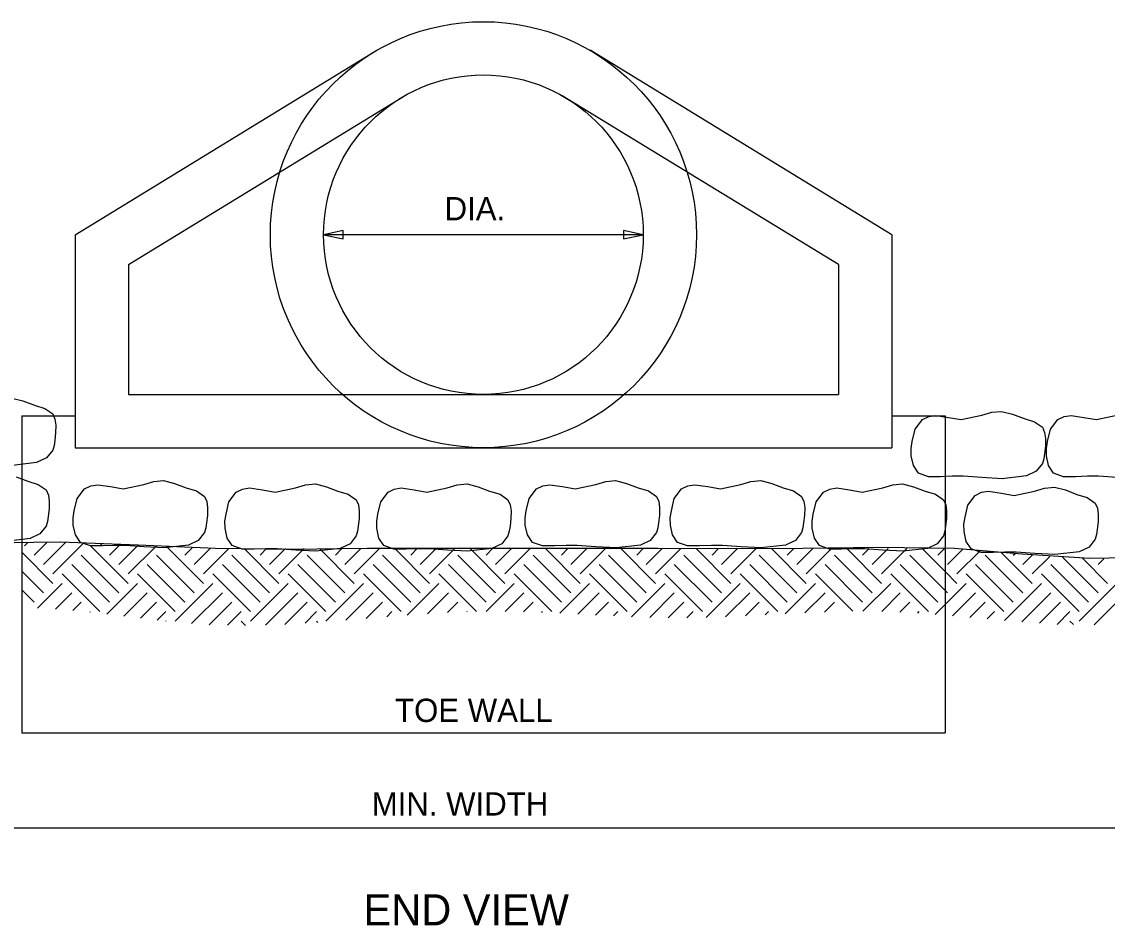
# Model space of a CAD drawing. Extents: x -439.1 to -407.9, y -458.1 to -436.2.
# Drawn here: x -431.65 to -424.66, y -450.95 to -445.13 of the extents above; entities that cross this region are included whole.
import ezdxf

# ---------------------------------------------------------------- set-up
doc = ezdxf.new("R2010")
doc.units = 0
doc.layers.add('Level 4', color=7, linetype='Continuous')

msp = doc.modelspace()

# ---------------------------------------------------------------- linework, layer by layer
at = {"layer": 'Level 4'}
for p, q in [((-431.3081, -446.4994), (-429.3651, -445.3119)), ((-426.0505, -446.4994), (-427.9935, -445.3119)), ((-430.9652, -446.6914), (-429.1868, -445.6045)), ((-426.3934, -446.6914), (-428.173, -445.6045)), ((-431.3081, -446.4994), (-431.3081, -447.8709)), ((-427.6512, -446.4993), (-429.7085, -446.4993)), ((-426.0505, -446.4994), (-426.0505, -447.8709)), ((-430.9652, -446.6914), (-430.9652, -447.528)), ((-426.3934, -446.6914), (-426.3934, -447.528)), ((-430.9652, -447.528), (-426.3934, -447.528)), ((-431.651, -447.6652), (-431.651, -449.7065)), ((-431.651, -447.6652), (-431.3081, -447.6652)), ((-426.0505, -447.6652), (-425.7076, -447.6652)), ((-425.7076, -447.6652), (-425.7076, -449.7065)), ((-431.3081, -447.8709), (-426.0505, -447.8709)), ((-431.6331, -448.502), (-431.6094, -448.4783)), ((-431.5725, -448.5626), (-431.4879, -448.478)), ((-431.5119, -448.6232), (-431.3677, -448.479)), ((-431.4513, -448.6838), (-431.2494, -448.4819)), ((-431.1482, -448.502), (-431.1327, -448.4864)), ((-431.4513, -448.7444), (-431.6515, -448.5442)), ((-430.9664, -448.7444), (-431.2088, -448.502)), ((-431.0876, -448.5626), (-431.0167, -448.4917)), ((-431.027, -448.6232), (-430.9012, -448.4975)), ((-430.9664, -448.6838), (-430.7861, -448.5036)), ((-430.4815, -448.7444), (-430.7188, -448.5071)), ((-430.6027, -448.5626), (-430.555, -448.5149)), ((-430.5421, -448.6232), (-430.4382, -448.5194)), ((-430.4815, -448.6838), (-430.3183, -448.5207)), ((-429.9965, -448.7444), (-430.2203, -448.5207)), ((-430.1178, -448.5626), (-430.0759, -448.5207)), ((-430.0571, -448.6232), (-429.9546, -448.5207)), ((-429.9965, -448.6838), (-429.8334, -448.5207)), ((-429.5116, -448.7444), (-429.7354, -448.5207)), ((-429.6328, -448.5626), (-429.5909, -448.5207)), ((-429.5722, -448.6232), (-429.4697, -448.5207)), ((-429.5116, -448.6838), (-429.3485, -448.5207)), ((-429.0267, -448.7444), (-429.2505, -448.5207)), ((-429.1479, -448.5626), (-429.106, -448.5207)), ((-429.0873, -448.6232), (-428.9848, -448.5207)), ((-429.0267, -448.6838), (-428.8636, -448.5207)), ((-428.5418, -448.7444), (-428.7656, -448.5207)), ((-428.663, -448.5626), (-428.6211, -448.5207)), ((-428.6024, -448.6232), (-428.4999, -448.5207)), ((-428.5418, -448.6838), (-428.3787, -448.5207)), ((-428.0569, -448.7444), (-428.2806, -448.5207)), ((-428.1781, -448.5626), (-428.1361, -448.5206)), ((-428.1175, -448.6232), (-428.0147, -448.5204)), ((-428.0569, -448.6838), (-427.8934, -448.5204)), ((-427.572, -448.7444), (-427.7961, -448.5203)), ((-427.6932, -448.5626), (-427.6511, -448.5205)), ((-427.6326, -448.6232), (-427.5301, -448.5207)), ((-427.572, -448.6838), (-427.4088, -448.5207)), ((-427.0871, -448.7444), (-427.3108, -448.5207)), ((-427.2083, -448.5626), (-427.1664, -448.5207)), ((-427.1477, -448.6232), (-427.0452, -448.5207)), ((-427.0871, -448.6838), (-426.9239, -448.5207)), ((-426.6021, -448.7444), (-426.8259, -448.5207)), ((-426.7234, -448.5626), (-426.6815, -448.5207)), ((-426.6628, -448.6232), (-426.5602, -448.5207)), ((-426.6021, -448.6838), (-426.439, -448.5207)), ((-426.1172, -448.7444), (-426.341, -448.5207)), ((-426.2385, -448.5626), (-426.1966, -448.5207)), ((-426.1779, -448.6232), (-426.0753, -448.5207)), ((-426.1172, -448.6838), (-425.9541, -448.5207)), ((-425.7081, -448.6686), (-425.8561, -448.5207)), ((-425.7536, -448.5626), (-425.7116, -448.5207)), ((-425.6929, -448.6232), (-425.5938, -448.524)), ((-425.6323, -448.6838), (-425.4807, -448.5322)), ((-425.1474, -448.7444), (-425.3484, -448.5435)), ((-425.2686, -448.5626), (-425.2577, -448.5517)), ((-431.0876, -448.8657), (-431.33, -448.6232)), ((-431.027, -448.8051), (-431.2694, -448.5626)), ((-430.6027, -448.8657), (-430.8451, -448.6232)), ((-430.5421, -448.8051), (-430.7845, -448.5626)), ((-430.1178, -448.8657), (-430.3602, -448.6232)), ((-430.0571, -448.8051), (-430.2996, -448.5626)), ((-429.6328, -448.8657), (-429.8753, -448.6232)), ((-429.5722, -448.8051), (-429.8147, -448.5626)), ((-429.1479, -448.8657), (-429.3904, -448.6232)), ((-429.0873, -448.8051), (-429.3298, -448.5626)), ((-428.663, -448.8657), (-428.9055, -448.6232)), ((-428.6024, -448.8051), (-428.8449, -448.5626)), ((-428.1781, -448.8657), (-428.4206, -448.6232)), ((-428.1175, -448.8051), (-428.36, -448.5626)), ((-427.6932, -448.8657), (-427.9357, -448.6232)), ((-427.6326, -448.8051), (-427.8751, -448.5626)), ((-427.2083, -448.8657), (-427.4508, -448.6232)), ((-427.1477, -448.8051), (-427.3901, -448.5626)), ((-426.7234, -448.8657), (-426.9658, -448.6232)), ((-426.6628, -448.8051), (-426.9052, -448.5626)), ((-426.2385, -448.8657), (-426.4809, -448.6232)), ((-426.1779, -448.8051), (-426.4203, -448.5626)), ((-425.7536, -448.8657), (-425.996, -448.6232)), ((-425.7081, -448.7899), (-425.9354, -448.5626)), ((-425.2686, -448.8657), (-425.5111, -448.6232)), ((-425.208, -448.8051), (-425.4505, -448.5626)), ((-425.208, -448.6232), (-425.1464, -448.5616)), ((-425.1474, -448.6838), (-425.0342, -448.5706)), ((-424.7837, -448.8657), (-425.0262, -448.6232)), ((-424.7231, -448.8051), (-424.9518, -448.5764)), ((-424.6625, -448.7444), (-424.8243, -448.5826)), ((-424.7231, -448.6232), (-424.6854, -448.5855)), ((-431.5119, -448.8051), (-431.6515, -448.6655)), ((-431.1482, -448.9263), (-431.3907, -448.6838)), ((-430.6633, -448.9263), (-430.9058, -448.6838)), ((-430.1784, -448.9263), (-430.4208, -448.6838)), ((-429.6935, -448.9263), (-429.9359, -448.6838)), ((-429.2086, -448.9263), (-429.451, -448.6838)), ((-428.7243, -448.9256), (-428.9661, -448.6838)), ((-428.2387, -448.9263), (-428.4812, -448.6838)), ((-427.7538, -448.9263), (-427.9963, -448.6838)), ((-427.2689, -448.9263), (-427.5114, -448.6838)), ((-426.784, -448.9263), (-427.0265, -448.6838)), ((-426.3011, -448.9242), (-426.5415, -448.6838)), ((-425.8142, -448.9263), (-426.0566, -448.6838)), ((-425.6323, -448.7444), (-425.7081, -448.6686)), ((-425.3293, -448.9263), (-425.5717, -448.6838)), ((-424.8444, -448.9263), (-425.0868, -448.6838)), ((-431.5492, -448.903), (-431.3907, -448.7444)), ((-431.1033, -448.942), (-430.9058, -448.7444)), ((-430.6633, -448.9869), (-430.4208, -448.7444)), ((-430.1784, -448.9869), (-429.9359, -448.7444)), ((-429.6935, -448.9869), (-429.451, -448.7444)), ((-429.1703, -448.9486), (-428.9661, -448.7444)), ((-428.6611, -448.9243), (-428.4812, -448.7444)), ((-428.1882, -448.9364), (-427.9963, -448.7444)), ((-427.7258, -448.9589), (-427.5114, -448.7444)), ((-427.2457, -448.9637), (-427.0265, -448.7444)), ((-426.7376, -448.9405), (-426.5415, -448.7444)), ((-426.2364, -448.9242), (-426.0566, -448.7444)), ((-425.7081, -448.8809), (-425.5717, -448.7444)), ((-425.3258, -448.9835), (-425.0868, -448.7444)), ((-424.8444, -448.9869), (-424.6019, -448.7444)), ((-431.5725, -448.8657), (-431.6515, -448.7867)), ((-431.4346, -448.9097), (-431.33, -448.8051)), ((-430.9953, -448.9553), (-430.8451, -448.8051)), ((-430.5586, -449.0034), (-430.3602, -448.8051)), ((-430.0825, -449.0123), (-429.8753, -448.8051)), ((-429.5663, -448.981), (-429.3904, -448.8051)), ((-429.0402, -448.9398), (-428.9055, -448.8051)), ((-428.5406, -448.9251), (-428.4206, -448.8051)), ((-428.0728, -448.9422), (-427.9357, -448.8051)), ((-427.6092, -448.9635), (-427.4508, -448.8051)), ((-427.1205, -448.9598), (-426.9658, -448.8051)), ((-426.6099, -448.934), (-426.4809, -448.8051)), ((-426.1159, -448.9249), (-425.996, -448.8051)), ((-425.6929, -448.8051), (-425.7081, -448.7899)), ((-425.6592, -448.9532), (-425.5111, -448.8051)), ((-425.214, -448.9929), (-425.0262, -448.8051)), ((-424.7475, -449.0113), (-424.5413, -448.8051)), ((-431.322, -448.9183), (-431.2694, -448.8657)), ((-430.8877, -448.9689), (-430.7845, -448.8657)), ((-430.4443, -449.0103), (-430.2996, -448.8657)), ((-429.9574, -449.0084), (-429.8147, -448.8657)), ((-429.4343, -448.9702), (-429.3298, -448.8657)), ((-428.9113, -448.9321), (-428.8449, -448.8657)), ((-428.4215, -448.9272), (-428.36, -448.8657)), ((-427.9575, -448.9481), (-427.8751, -448.8657)), ((-427.4897, -448.9653), (-427.3901, -448.8657)), ((-426.9937, -448.9541), (-426.9052, -448.8657)), ((-426.4835, -448.9288), (-426.4203, -448.8657)), ((-425.9993, -448.9296), (-425.9354, -448.8657)), ((-425.7712, -448.9439), (-425.7081, -448.8809)), ((-425.548, -448.9632), (-425.4505, -448.8657)), ((-425.1011, -449.0012), (-424.9656, -448.8657)), ((-431.2117, -448.9292), (-431.2088, -448.9263)), ((-430.7794, -448.9817), (-430.7239, -448.9263)), ((-430.3263, -449.0136), (-430.239, -448.9263)), ((-429.8281, -449.0003), (-429.7541, -448.9263)), ((-429.302, -448.9591), (-429.2692, -448.9263)), ((-428.7857, -448.9277), (-428.7843, -448.9263)), ((-428.3044, -448.9313), (-428.2993, -448.9263)), ((-427.8422, -448.9541), (-427.8144, -448.9263)), ((-427.3695, -448.9663), (-427.3295, -448.9263)), ((-426.8657, -448.9474), (-426.8446, -448.9263)), ((-425.8844, -448.9359), (-425.8748, -448.9263)), ((-425.437, -448.9734), (-425.3899, -448.9263)), ((-424.9867, -449.008), (-424.905, -448.9263)), ((-430.7227, -448.9882), (-430.7239, -448.9869)), ((-430.2102, -449.0156), (-430.239, -448.9869)), ((-429.7459, -448.9951), (-429.7541, -448.9869)), ((-424.8819, -449.01), (-424.905, -448.9869)), ((-431.651, -449.7065), (-425.7076, -449.7065)), ((-421.7952, -450.3206), (-435.8524, -450.3206))]:
    msp.add_line(p, q, dxfattribs=at)
for points in [[(-429.582, -446.473), (-429.7085, -446.4993), (-429.582, -446.5255)], [(-427.7776, -446.5255), (-427.6512, -446.4993), (-427.7776, -446.473)], [(-425.9192, -447.8304), (-425.9008, -447.7518), (-425.8534, -447.6891), (-425.8131, -447.6696), (-425.768, -447.6629), (-425.6852, -447.6752), (-425.6037, -447.6891), (-425.4724, -447.6612), (-425.4074, -447.6424), (-425.3441, -447.6366), (-425.2735, -447.6546), (-425.1996, -447.6826), (-425.1324, -447.7035), (-425.0813, -447.7384), (-425.0669, -447.772), (-425.0616, -447.8107), (-425.0626, -447.8603), (-425.0681, -447.9093), (-425.0729, -447.9415), (-425.0813, -447.9717), (-425.1212, -448.0216), (-425.1847, -448.0517), (-425.3408, -448.0703), (-425.4708, -448.0631), (-425.5906, -448.0539), (-425.6623, -448.054), (-425.7384, -448.0572), (-425.8155, -448.0572), (-425.8797, -448.0342), (-425.912, -447.9852), (-425.9257, -447.9224), (-425.9265, -447.8755), (-425.9192, -447.8304)], [(-431.3132, -448.2764), (-431.2949, -448.1978), (-431.2475, -448.1351), (-431.2071, -448.1156), (-431.1621, -448.1088), (-431.0793, -448.1212), (-430.9978, -448.1351), (-430.8665, -448.1072), (-430.8015, -448.0884), (-430.7382, -448.0825), (-430.6676, -448.1006), (-430.5936, -448.1285), (-430.5265, -448.1494), (-430.4753, -448.1844), (-430.461, -448.218), (-430.4556, -448.2567), (-430.4566, -448.3063), (-430.4622, -448.3553), (-430.467, -448.3875), (-430.4753, -448.4177), (-430.5153, -448.4676), (-430.5787, -448.4976), (-430.7349, -448.5163), (-430.8649, -448.509), (-430.9847, -448.4998), (-431.0564, -448.4999), (-431.1325, -448.5031), (-431.2096, -448.5031), (-431.2738, -448.4801), (-431.306, -448.4312), (-431.3198, -448.3684), (-431.3206, -448.3215), (-431.3132, -448.2764)], [(-430.3364, -448.2976), (-430.318, -448.219), (-430.2706, -448.1564), (-430.2303, -448.1368), (-430.1852, -448.1301), (-430.1024, -448.1424), (-430.0209, -448.1564), (-429.8896, -448.1284), (-429.8246, -448.1096), (-429.7613, -448.1038), (-429.6907, -448.1218), (-429.6168, -448.1498), (-429.5496, -448.1707), (-429.4985, -448.2056), (-429.4841, -448.2393), (-429.4788, -448.2779), (-429.4798, -448.3275), (-429.4853, -448.3765), (-429.4901, -448.4087), (-429.4985, -448.4389), (-429.5384, -448.4888), (-429.6019, -448.5189), (-429.758, -448.5375), (-429.888, -448.5303), (-430.0078, -448.5211), (-430.0795, -448.5212), (-430.1556, -448.5244), (-430.2327, -448.5244), (-430.2969, -448.5014), (-430.3292, -448.4524), (-430.3429, -448.3896), (-430.3437, -448.3427), (-430.3364, -448.2976)], [(-429.3595, -448.2976), (-429.3411, -448.219), (-429.2938, -448.1564), (-429.2534, -448.1368), (-429.2083, -448.1301), (-429.1255, -448.1424), (-429.044, -448.1564), (-428.9127, -448.1284), (-428.8477, -448.1096), (-428.7844, -448.1038), (-428.7139, -448.1218), (-428.6399, -448.1498), (-428.5727, -448.1707), (-428.5216, -448.2056), (-428.5072, -448.2393), (-428.5019, -448.2779), (-428.5029, -448.3275), (-428.5084, -448.3765), (-428.5132, -448.4087), (-428.5216, -448.4389), (-428.5615, -448.4888), (-428.625, -448.5189), (-428.7812, -448.5375), (-428.9111, -448.5303), (-429.0309, -448.5211), (-429.1026, -448.5212), (-429.1788, -448.5244), (-429.2559, -448.5244), (-429.32, -448.5014), (-429.3523, -448.4524), (-429.366, -448.3896), (-429.3668, -448.3427), (-429.3595, -448.2976)], [(-428.4038, -448.2764), (-428.3855, -448.1978), (-428.3381, -448.1351), (-428.2977, -448.1156), (-428.2527, -448.1088), (-428.1699, -448.1212), (-428.0884, -448.1351), (-427.9571, -448.1072), (-427.8921, -448.0884), (-427.8288, -448.0825), (-427.7582, -448.1006), (-427.6842, -448.1285), (-427.6171, -448.1494), (-427.5659, -448.1844), (-427.5515, -448.218), (-427.5462, -448.2567), (-427.5472, -448.3063), (-427.5528, -448.3553), (-427.5576, -448.3875), (-427.5659, -448.4177), (-427.6059, -448.4676), (-427.6693, -448.4976), (-427.8255, -448.5163), (-427.9555, -448.509), (-428.0752, -448.4998), (-428.147, -448.4999), (-428.2231, -448.5031), (-428.3002, -448.5031), (-428.3644, -448.4801), (-428.3966, -448.4312), (-428.4104, -448.3684), (-428.4112, -448.3215), (-428.4038, -448.2764)], [(-427.4694, -448.2764), (-427.4511, -448.1978), (-427.4037, -448.1351), (-427.3633, -448.1156), (-427.3183, -448.1088), (-427.2355, -448.1212), (-427.154, -448.1351), (-427.0227, -448.1072), (-426.9577, -448.0884), (-426.8944, -448.0825), (-426.8238, -448.1006), (-426.7498, -448.1285), (-426.6827, -448.1494), (-426.6315, -448.1844), (-426.6171, -448.218), (-426.6118, -448.2567), (-426.6128, -448.3063), (-426.6184, -448.3553), (-426.6232, -448.3875), (-426.6315, -448.4177), (-426.6715, -448.4676), (-426.7349, -448.4976), (-426.8911, -448.5163), (-427.0211, -448.509), (-427.1408, -448.4998), (-427.2126, -448.4999), (-427.2887, -448.5031), (-427.3658, -448.5031), (-427.43, -448.4801), (-427.4622, -448.4312), (-427.476, -448.3684), (-427.4768, -448.3215), (-427.4694, -448.2764)], [(-426.5563, -448.2976), (-426.5379, -448.219), (-426.4905, -448.1564), (-426.4502, -448.1368), (-426.4051, -448.1301), (-426.3223, -448.1424), (-426.2408, -448.1564), (-426.1095, -448.1284), (-426.0445, -448.1096), (-425.9812, -448.1038), (-425.9106, -448.1218), (-425.8367, -448.1498), (-425.7695, -448.1707), (-425.7184, -448.2056), (-425.704, -448.2393), (-425.6986, -448.2779), (-425.6996, -448.3275), (-425.7052, -448.3765), (-425.71, -448.4087), (-425.7184, -448.4389), (-425.7583, -448.4888), (-425.8218, -448.5189), (-425.9779, -448.5375), (-426.1079, -448.5303), (-426.2277, -448.5211), (-426.2994, -448.5212), (-426.3755, -448.5244), (-426.4526, -448.5244), (-426.5168, -448.5014), (-426.5491, -448.4524), (-426.5628, -448.3896), (-426.5636, -448.3427), (-426.5563, -448.2976)], [(-425.5794, -448.3189), (-425.561, -448.2403), (-425.5137, -448.1776), (-425.4733, -448.158), (-425.4282, -448.1513), (-425.3454, -448.1636), (-425.2639, -448.1776), (-425.1326, -448.1497), (-425.0676, -448.1309), (-425.0043, -448.125), (-424.9338, -448.143), (-424.8598, -448.171), (-424.7926, -448.1919), (-424.7415, -448.2269), (-424.7271, -448.2605), (-424.7218, -448.2992), (-424.7228, -448.3488), (-424.7283, -448.3977), (-424.7331, -448.43), (-424.7415, -448.4602), (-424.7814, -448.5101), (-424.8449, -448.5401), (-425.0011, -448.5587), (-425.131, -448.5515), (-425.2508, -448.5423), (-425.3225, -448.5424), (-425.3987, -448.5456), (-425.4758, -448.5456), (-425.5399, -448.5226), (-425.5722, -448.4736), (-425.5859, -448.4109), (-425.5867, -448.364), (-425.5794, -448.3189)]]:
    msp.add_lwpolyline(points, close=True, dxfattribs=at)
for points in [[(-431.7151, -447.5516), (-431.6445, -447.5697), (-431.5705, -447.5976), (-431.5034, -447.6185), (-431.4522, -447.6535), (-431.4378, -447.6871), (-431.4325, -447.7258), (-431.4335, -447.7754), (-431.4391, -447.8244), (-431.4439, -447.8566), (-431.4522, -447.8868), (-431.4922, -447.9367), (-431.5556, -447.9667), (-431.7118, -447.9854)], [(-424.6001, -448.0631), (-424.7199, -448.0539), (-424.7916, -448.054), (-424.8677, -448.0572), (-424.9448, -448.0572), (-425.009, -448.0342), (-425.0413, -447.9852), (-425.055, -447.9224), (-425.0558, -447.8755), (-425.0485, -447.8304), (-425.0485, -447.8304), (-425.0301, -447.7518), (-424.9827, -447.6891), (-424.9424, -447.6696), (-424.8973, -447.6629), (-424.8145, -447.6752), (-424.733, -447.6891), (-424.6017, -447.6612)], [(-431.687, -448.0581), (-431.613, -448.0861), (-431.5459, -448.1069), (-431.4947, -448.1419), (-431.4803, -448.1755), (-431.475, -448.2142), (-431.476, -448.2638), (-431.4815, -448.3128), (-431.4863, -448.345), (-431.4947, -448.3752), (-431.5346, -448.4251), (-431.5981, -448.4552), (-431.7543, -448.4738)], [(-424.2877, -448.5747), (-424.7758, -448.5844), (-425.2111, -448.5559), (-425.6465, -448.5207), (-426.1347, -448.5123), (-426.6234, -448.5207), (-427.0906, -448.5227), (-427.5578, -448.5207), (-428.0144, -448.5204), (-428.471, -448.5207), (-428.9488, -448.5196), (-429.4266, -448.5207), (-429.9151, -448.5253), (-430.4035, -448.5207), (-430.9026, -448.4974), (-431.4016, -448.4782), (-431.9218, -448.485)]]:
    msp.add_lwpolyline(points, dxfattribs=at)
for radius in [1.3715, 1.0287]:
    msp.add_circle((-428.6798, -446.4993), radius, dxfattribs=at)

# ---------------------------------------------------------------- texts
for s, height, p in [('DIA.', 0.15, (-428.9296, -446.4065)), ('TOE WALL', 0.15, (-429.2486, -449.6367)), ('MIN. WIDTH', 0.15, (-429.3986, -450.2392)), ('END VIEW', 0.2, (-429.4514, -450.9458))]:
    msp.add_text(s, height=height, dxfattribs=at).set_placement(p)

doc.saveas('drawing.dxf')
